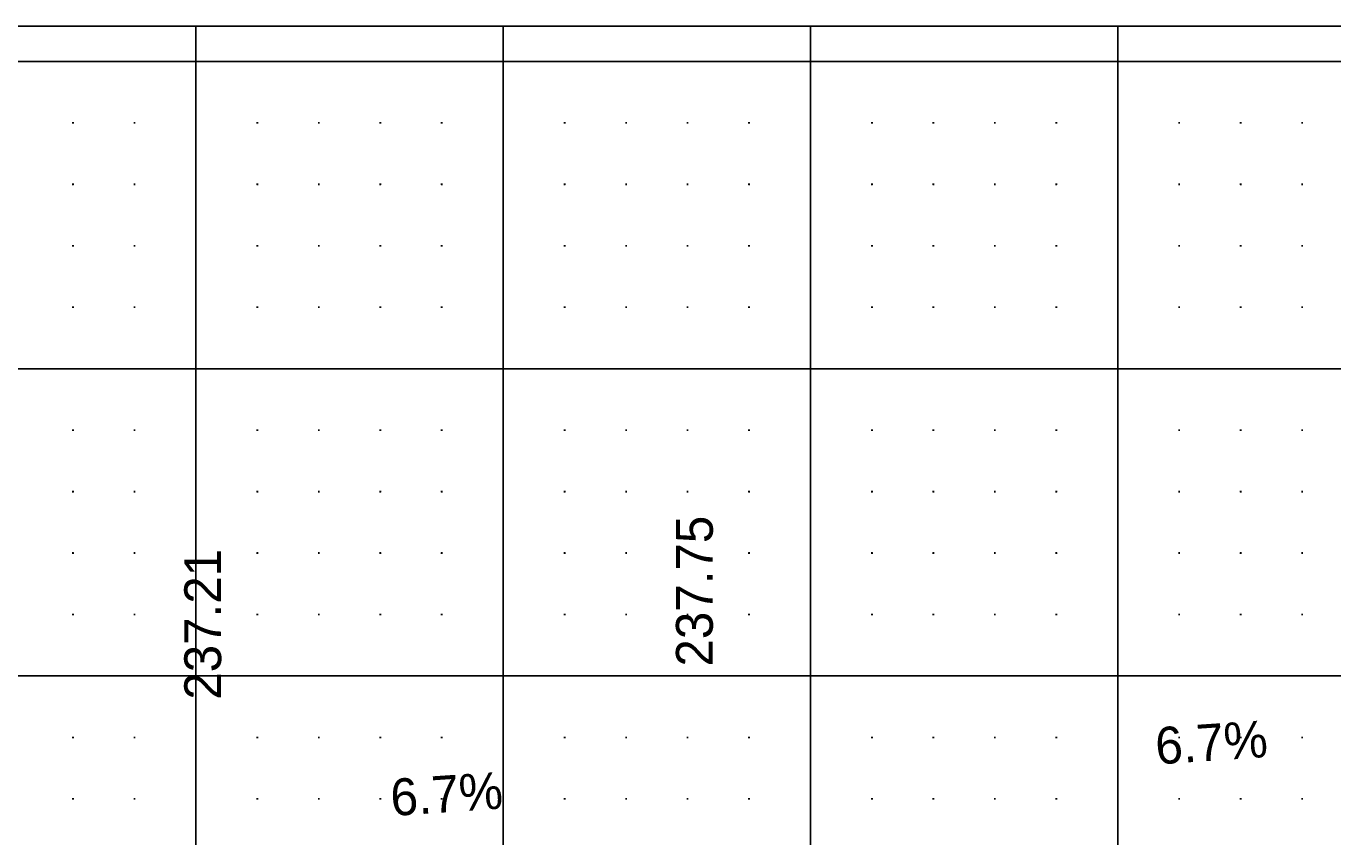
# Model space of a CAD drawing. Extents: x -80 to 80, y 222 to 253.
# Drawn here: x -27.76 to -6.5, y 237.38 to 250.57 of the extents above; entities that cross this region are included whole.
import ezdxf

# ---------------------------------------------------------------- set-up
doc = ezdxf.new("R2010")
doc.units = 0
for name, color, linetype in [('DSN_DRFT_XS Border Grid', 7, 'Continuous'), ('DSN_DRFT_XS Grid Major', 7, 'Continuous'), ('DSN_DRFT_XS Grid Minor', 7, 'Continuous'), ('DSN_RDWY_XS Annotation', 7, 'Continuous')]:
    doc.layers.add(name, color=color, linetype=linetype)

msp = doc.modelspace()

# ---------------------------------------------------------------- linework, layer by layer
at = {"layer": 'DSN_DRFT_XS Border Grid'}
msp.add_line((-77.5, 250.573), (77.5, 250.573), dxfattribs=at)
at = {"layer": 'DSN_DRFT_XS Grid Major'}
for p, q in [((-25, 226), (-25, 250.573)), ((-20, 226), (-20, 250.573)), ((-15, 226), (-15, 250.573)), ((-10, 226), (-10, 250.573)), ((-77.5, 250), (77.5, 250)), ((-77.5, 245), (77.5, 245)), ((-77.5, 240), (77.5, 240))]:
    msp.add_line(p, q, dxfattribs=at)
at = {"layer": 'DSN_DRFT_XS Grid Minor'}
for p, q in [((-26.988, 249), (-27.012, 249)), ((-27, 249.012), (-27, 248.988)), ((-25.988, 249), (-26.012, 249)), ((-26, 249.012), (-26, 248.988)), ((-23.988, 249), (-24.012, 249)), ((-24, 249.012), (-24, 248.988)), ((-22.988, 249), (-23.012, 249)), ((-23, 249.012), (-23, 248.988)), ((-21.988, 249), (-22.012, 249)), ((-22, 249.012), (-22, 248.988)), ((-20.988, 249), (-21.012, 249)), ((-21, 249.012), (-21, 248.988)), ((-18.988, 249), (-19.012, 249)), ((-19, 249.012), (-19, 248.988)), ((-17.988, 249), (-18.012, 249)), ((-18, 249.012), (-18, 248.988)), ((-16.988, 249), (-17.012, 249)), ((-17, 249.012), (-17, 248.988)), ((-15.988, 249), (-16.012, 249)), ((-16, 249.012), (-16, 248.988)), ((-13.988, 249), (-14.012, 249)), ((-14, 249.012), (-14, 248.988)), ((-12.988, 249), (-13.012, 249)), ((-13, 249.012), (-13, 248.988)), ((-11.988, 249), (-12.012, 249)), ((-12, 249.012), (-12, 248.988)), ((-10.988, 249), (-11.012, 249)), ((-11, 249.012), (-11, 248.988)), ((-8.988, 249), (-9.012, 249)), ((-9, 249.012), (-9, 248.988)), ((-7.988, 249), (-8.012, 249)), ((-8, 249.012), (-8, 248.988)), ((-6.988, 249), (-7.012, 249)), ((-7, 249.012), (-7, 248.988)), ((-26.988, 248), (-27.012, 248)), ((-27, 248.012), (-27, 247.988)), ((-25.988, 248), (-26.012, 248)), ((-26, 248.012), (-26, 247.988)), ((-23.988, 248), (-24.012, 248)), ((-24, 248.012), (-24, 247.988)), ((-22.988, 248), (-23.012, 248)), ((-23, 248.012), (-23, 247.988)), ((-21.988, 248), (-22.012, 248)), ((-22, 248.012), (-22, 247.988)), ((-20.988, 248), (-21.012, 248)), ((-21, 248.012), (-21, 247.988)), ((-18.988, 248), (-19.012, 248)), ((-19, 248.012), (-19, 247.988)), ((-17.988, 248), (-18.012, 248)), ((-18, 248.012), (-18, 247.988)), ((-16.988, 248), (-17.012, 248)), ((-17, 248.012), (-17, 247.988)), ((-15.988, 248), (-16.012, 248)), ((-16, 248.012), (-16, 247.988)), ((-13.988, 248), (-14.012, 248)), ((-14, 248.012), (-14, 247.988)), ((-12.988, 248), (-13.012, 248)), ((-13, 248.012), (-13, 247.988)), ((-11.988, 248), (-12.012, 248)), ((-12, 248.012), (-12, 247.988)), ((-10.988, 248), (-11.012, 248)), ((-11, 248.012), (-11, 247.988)), ((-8.988, 248), (-9.012, 248)), ((-9, 248.012), (-9, 247.988)), ((-7.988, 248), (-8.012, 248)), ((-8, 248.012), (-8, 247.988)), ((-6.988, 248), (-7.012, 248)), ((-7, 248.012), (-7, 247.988)), ((-26.988, 247), (-27.012, 247)), ((-27, 247.012), (-27, 246.988)), ((-25.988, 247), (-26.012, 247)), ((-26, 247.012), (-26, 246.988)), ((-23.988, 247), (-24.012, 247)), ((-24, 247.012), (-24, 246.988)), ((-22.988, 247), (-23.012, 247)), ((-23, 247.012), (-23, 246.988)), ((-21.988, 247), (-22.012, 247)), ((-22, 247.012), (-22, 246.988)), ((-20.988, 247), (-21.012, 247)), ((-21, 247.012), (-21, 246.988)), ((-18.988, 247), (-19.012, 247)), ((-19, 247.012), (-19, 246.988)), ((-17.988, 247), (-18.012, 247)), ((-18, 247.012), (-18, 246.988)), ((-16.988, 247), (-17.012, 247)), ((-17, 247.012), (-17, 246.988)), ((-15.988, 247), (-16.012, 247)), ((-16, 247.012), (-16, 246.988)), ((-13.988, 247), (-14.012, 247)), ((-14, 247.012), (-14, 246.988)), ((-12.988, 247), (-13.012, 247)), ((-13, 247.012), (-13, 246.988)), ((-11.988, 247), (-12.012, 247)), ((-12, 247.012), (-12, 246.988)), ((-10.988, 247), (-11.012, 247)), ((-11, 247.012), (-11, 246.988)), ((-8.988, 247), (-9.012, 247)), ((-9, 247.012), (-9, 246.988)), ((-7.988, 247), (-8.012, 247)), ((-8, 247.012), (-8, 246.988)), ((-6.988, 247), (-7.012, 247)), ((-7, 247.012), (-7, 246.988)), ((-27, 246.012), (-27, 245.988)), ((-26, 246.012), (-26, 245.988)), ((-24, 246.012), (-24, 245.988)), ((-23, 246.012), (-23, 245.988)), ((-22, 246.012), (-22, 245.988)), ((-21, 246.012), (-21, 245.988)), ((-19, 246.012), (-19, 245.988)), ((-18, 246.012), (-18, 245.988)), ((-17, 246.012), (-17, 245.988)), ((-16, 246.012), (-16, 245.988)), ((-14, 246.012), (-14, 245.988)), ((-13, 246.012), (-13, 245.988)), ((-12, 246.012), (-12, 245.988)), ((-11, 246.012), (-11, 245.988)), ((-9, 246.012), (-9, 245.988)), ((-8, 246.012), (-8, 245.988)), ((-7, 246.012), (-7, 245.988)), ((-26.988, 246), (-27.012, 246)), ((-25.988, 246), (-26.012, 246)), ((-23.988, 246), (-24.012, 246)), ((-22.988, 246), (-23.012, 246)), ((-21.988, 246), (-22.012, 246)), ((-20.988, 246), (-21.012, 246)), ((-18.988, 246), (-19.012, 246)), ((-17.988, 246), (-18.012, 246)), ((-16.988, 246), (-17.012, 246)), ((-15.988, 246), (-16.012, 246)), ((-13.988, 246), (-14.012, 246)), ((-12.988, 246), (-13.012, 246)), ((-11.988, 246), (-12.012, 246)), ((-10.988, 246), (-11.012, 246)), ((-8.988, 246), (-9.012, 246)), ((-7.988, 246), (-8.012, 246)), ((-6.988, 246), (-7.012, 246)), ((-26.988, 244), (-27.012, 244)), ((-27, 244.012), (-27, 243.988)), ((-25.988, 244), (-26.012, 244)), ((-26, 244.012), (-26, 243.988)), ((-23.988, 244), (-24.012, 244)), ((-24, 244.012), (-24, 243.988)), ((-22.988, 244), (-23.012, 244)), ((-23, 244.012), (-23, 243.988)), ((-21.988, 244), (-22.012, 244)), ((-22, 244.012), (-22, 243.988)), ((-20.988, 244), (-21.012, 244)), ((-21, 244.012), (-21, 243.988)), ((-18.988, 244), (-19.012, 244)), ((-19, 244.012), (-19, 243.988)), ((-17.988, 244), (-18.012, 244)), ((-18, 244.012), (-18, 243.988)), ((-16.988, 244), (-17.012, 244)), ((-17, 244.012), (-17, 243.988)), ((-15.988, 244), (-16.012, 244)), ((-16, 244.012), (-16, 243.988)), ((-13.988, 244), (-14.012, 244)), ((-14, 244.012), (-14, 243.988)), ((-12.988, 244), (-13.012, 244)), ((-13, 244.012), (-13, 243.988)), ((-11.988, 244), (-12.012, 244)), ((-12, 244.012), (-12, 243.988)), ((-10.988, 244), (-11.012, 244)), ((-11, 244.012), (-11, 243.988)), ((-8.988, 244), (-9.012, 244)), ((-9, 244.012), (-9, 243.988)), ((-7.988, 244), (-8.012, 244)), ((-8, 244.012), (-8, 243.988)), ((-6.988, 244), (-7.012, 244)), ((-7, 244.012), (-7, 243.988)), ((-26.988, 243), (-27.012, 243)), ((-27, 243.012), (-27, 242.988)), ((-25.988, 243), (-26.012, 243)), ((-26, 243.012), (-26, 242.988)), ((-23.988, 243), (-24.012, 243)), ((-24, 243.012), (-24, 242.988)), ((-22.988, 243), (-23.012, 243)), ((-23, 243.012), (-23, 242.988)), ((-21.988, 243), (-22.012, 243)), ((-22, 243.012), (-22, 242.988)), ((-20.988, 243), (-21.012, 243)), ((-21, 243.012), (-21, 242.988)), ((-18.988, 243), (-19.012, 243)), ((-19, 243.012), (-19, 242.988)), ((-17.988, 243), (-18.012, 243)), ((-18, 243.012), (-18, 242.988)), ((-16.988, 243), (-17.012, 243)), ((-17, 243.012), (-17, 242.988)), ((-15.988, 243), (-16.012, 243)), ((-16, 243.012), (-16, 242.988)), ((-13.988, 243), (-14.012, 243)), ((-14, 243.012), (-14, 242.988)), ((-12.988, 243), (-13.012, 243)), ((-13, 243.012), (-13, 242.988)), ((-11.988, 243), (-12.012, 243)), ((-12, 243.012), (-12, 242.988)), ((-10.988, 243), (-11.012, 243)), ((-11, 243.012), (-11, 242.988)), ((-8.988, 243), (-9.012, 243)), ((-9, 243.012), (-9, 242.988)), ((-7.988, 243), (-8.012, 243)), ((-8, 243.012), (-8, 242.988)), ((-6.988, 243), (-7.012, 243)), ((-7, 243.012), (-7, 242.988)), ((-26.988, 242), (-27.012, 242)), ((-27, 242.012), (-27, 241.988)), ((-25.988, 242), (-26.012, 242)), ((-26, 242.012), (-26, 241.988)), ((-23.988, 242), (-24.012, 242)), ((-24, 242.012), (-24, 241.988)), ((-22.988, 242), (-23.012, 242)), ((-23, 242.012), (-23, 241.988)), ((-21.988, 242), (-22.012, 242)), ((-22, 242.012), (-22, 241.988)), ((-20.988, 242), (-21.012, 242)), ((-21, 242.012), (-21, 241.988)), ((-18.988, 242), (-19.012, 242)), ((-19, 242.012), (-19, 241.988)), ((-17.988, 242), (-18.012, 242)), ((-18, 242.012), (-18, 241.988)), ((-16.988, 242), (-17.012, 242)), ((-17, 242.012), (-17, 241.988)), ((-15.988, 242), (-16.012, 242)), ((-16, 242.012), (-16, 241.988)), ((-13.988, 242), (-14.012, 242)), ((-14, 242.012), (-14, 241.988)), ((-12.988, 242), (-13.012, 242)), ((-13, 242.012), (-13, 241.988)), ((-11.988, 242), (-12.012, 242)), ((-12, 242.012), (-12, 241.988)), ((-10.988, 242), (-11.012, 242)), ((-11, 242.012), (-11, 241.988)), ((-8.988, 242), (-9.012, 242)), ((-9, 242.012), (-9, 241.988)), ((-7.988, 242), (-8.012, 242)), ((-8, 242.012), (-8, 241.988)), ((-6.988, 242), (-7.012, 242)), ((-7, 242.012), (-7, 241.988)), ((-26.988, 241), (-27.012, 241)), ((-27, 241.012), (-27, 240.988)), ((-25.988, 241), (-26.012, 241)), ((-26, 241.012), (-26, 240.988)), ((-23.988, 241), (-24.012, 241)), ((-24, 241.012), (-24, 240.988)), ((-22.988, 241), (-23.012, 241)), ((-23, 241.012), (-23, 240.988)), ((-21.988, 241), (-22.012, 241)), ((-22, 241.012), (-22, 240.988)), ((-20.988, 241), (-21.012, 241)), ((-21, 241.012), (-21, 240.988)), ((-18.988, 241), (-19.012, 241)), ((-19, 241.012), (-19, 240.988)), ((-17.988, 241), (-18.012, 241)), ((-18, 241.012), (-18, 240.988)), ((-16.988, 241), (-17.012, 241)), ((-17, 241.012), (-17, 240.988)), ((-15.988, 241), (-16.012, 241)), ((-16, 241.012), (-16, 240.988)), ((-13.988, 241), (-14.012, 241)), ((-14, 241.012), (-14, 240.988)), ((-12.988, 241), (-13.012, 241)), ((-13, 241.012), (-13, 240.988)), ((-11.988, 241), (-12.012, 241)), ((-12, 241.012), (-12, 240.988)), ((-10.988, 241), (-11.012, 241)), ((-11, 241.012), (-11, 240.988)), ((-8.988, 241), (-9.012, 241)), ((-9, 241.012), (-9, 240.988)), ((-7.988, 241), (-8.012, 241)), ((-8, 241.012), (-8, 240.988)), ((-6.988, 241), (-7.012, 241)), ((-7, 241.012), (-7, 240.988)), ((-26.988, 239), (-27.012, 239)), ((-27, 239.012), (-27, 238.988)), ((-25.988, 239), (-26.012, 239)), ((-26, 239.012), (-26, 238.988)), ((-23.988, 239), (-24.012, 239)), ((-24, 239.012), (-24, 238.988)), ((-22.988, 239), (-23.012, 239)), ((-23, 239.012), (-23, 238.988)), ((-21.988, 239), (-22.012, 239)), ((-22, 239.012), (-22, 238.988)), ((-20.988, 239), (-21.012, 239)), ((-21, 239.012), (-21, 238.988)), ((-18.988, 239), (-19.012, 239)), ((-19, 239.012), (-19, 238.988)), ((-17.988, 239), (-18.012, 239)), ((-18, 239.012), (-18, 238.988)), ((-16.988, 239), (-17.012, 239)), ((-17, 239.012), (-17, 238.988)), ((-15.988, 239), (-16.012, 239)), ((-16, 239.012), (-16, 238.988)), ((-13.988, 239), (-14.012, 239)), ((-14, 239.012), (-14, 238.988)), ((-12.988, 239), (-13.012, 239)), ((-13, 239.012), (-13, 238.988)), ((-11.988, 239), (-12.012, 239)), ((-12, 239.012), (-12, 238.988)), ((-10.988, 239), (-11.012, 239)), ((-11, 239.012), (-11, 238.988)), ((-8.988, 239), (-9.012, 239)), ((-9, 239.012), (-9, 238.988)), ((-7.988, 239), (-8.012, 239)), ((-8, 239.012), (-8, 238.988)), ((-6.988, 239), (-7.012, 239)), ((-7, 239.012), (-7, 238.988)), ((-26.988, 238), (-27.012, 238)), ((-27, 238.012), (-27, 237.988)), ((-25.988, 238), (-26.012, 238)), ((-26, 238.012), (-26, 237.988)), ((-23.988, 238), (-24.012, 238)), ((-24, 238.012), (-24, 237.988)), ((-22.988, 238), (-23.012, 238)), ((-23, 238.012), (-23, 237.988)), ((-21.988, 238), (-22.012, 238)), ((-22, 238.012), (-22, 237.988)), ((-20.988, 238), (-21.012, 238)), ((-21, 238.012), (-21, 237.988)), ((-18.988, 238), (-19.012, 238)), ((-19, 238.012), (-19, 237.988)), ((-17.988, 238), (-18.012, 238)), ((-18, 238.012), (-18, 237.988)), ((-16.988, 238), (-17.012, 238)), ((-17, 238.012), (-17, 237.988)), ((-15.988, 238), (-16.012, 238)), ((-16, 238.012), (-16, 237.988)), ((-13.988, 238), (-14.012, 238)), ((-14, 238.012), (-14, 237.988)), ((-12.988, 238), (-13.012, 238)), ((-13, 238.012), (-13, 237.988)), ((-11.988, 238), (-12.012, 238)), ((-12, 238.012), (-12, 237.988)), ((-10.988, 238), (-11.012, 238)), ((-11, 238.012), (-11, 237.988)), ((-8.988, 238), (-9.012, 238)), ((-9, 238.012), (-9, 237.988)), ((-7.988, 238), (-8.012, 238)), ((-8, 238.012), (-8, 237.988)), ((-6.988, 238), (-7.012, 238)), ((-7, 238.012), (-7, 237.988))]:
    msp.add_line(p, q, dxfattribs=at)

# ---------------------------------------------------------------- texts
at = {"layer": 'DSN_RDWY_XS Annotation'}
for s, rotation, p in [('237.75', 90, (-16.589, 240.153)), ('237.21', 90, (-24.589, 239.614)), ('6.7%', 3.8537, (-9.369, 238.56)), ('6.7%', 3.8537, (-9.369, 238.56)), ('6.7%', 3.8537, (-21.814, 237.721))]:
    msp.add_text(s, height=0.6, rotation=rotation, dxfattribs=at).set_placement(p)

doc.saveas('drawing.dxf')
